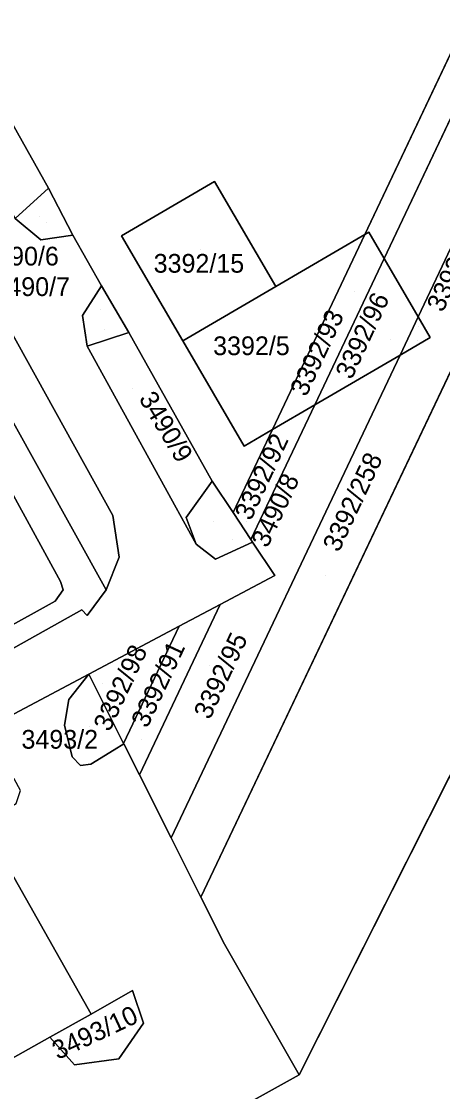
# Model space of a CAD drawing. Extents: x -262715 to -259381, y -1237238 to -1231182.
# Drawn here: x -261261.3 to -261216.3, y -1235699.9 to -1235585.6 of the extents above; entities that cross this region are included whole.
import ezdxf

# ---------------------------------------------------------------- set-up
doc = ezdxf.new("R2010")
doc.units = 0
for name, color, linetype in [('body_kn', 7, 'Continuous'), ('kladpar_druhypozemkov', 7, 'Continuous'), ('kladpar_hranice', 7, 'Continuous'), ('kladpar_parcelnecisla', 7, 'Continuous'), ('kladpar_plochy', 7, 'Continuous'), ('kladpar_sipky', 7, 'Continuous'), ('zuob_linie', 7, 'Continuous'), ('zuob_plochy', 7, 'Continuous')]:
    doc.layers.add(name, color=color, linetype=linetype)

msp = doc.modelspace()

# ---------------------------------------------------------------- linework, layer by layer
at = {"layer": 'body_kn'}
for p, q in [((-261240.67, -1235602.69), (-261240.67, -1235602.69)), ((-261258.41, -1235603.43), (-261258.41, -1235603.43)), ((-261258.41, -1235603.43), (-261258.41, -1235603.43)), ((-261224.62, -1235608.37), (-261224.62, -1235608.37)), ((-261224.62, -1235608.37), (-261224.62, -1235608.37)), ((-261224.19, -1235608.12), (-261224.19, -1235608.12)), ((-261259.21, -1235608.94), (-261259.21, -1235608.94)), ((-261255.82, -1235608.45), (-261255.82, -1235608.45)), ((-261250.6, -1235608.49), (-261250.6, -1235608.49)), ((-261250.6, -1235608.49), (-261250.6, -1235608.49)), ((-261222.56, -1235610.92), (-261222.56, -1235610.92)), ((-261252.75, -1235613.83), (-261252.75, -1235613.83)), ((-261252.75, -1235613.83), (-261252.75, -1235613.83)), ((-261234.12, -1235613.92), (-261234.12, -1235613.92)), ((-261254.78, -1235617), (-261254.78, -1235617)), ((-261218.92, -1235617.15), (-261218.92, -1235617.15)), ((-261218.92, -1235617.15), (-261218.92, -1235617.15)), ((-261249.83, -1235618.82), (-261249.83, -1235618.82)), ((-261249.83, -1235618.82), (-261249.83, -1235618.82)), ((-261244.05, -1235619.72), (-261244.05, -1235619.72)), ((-261217.63, -1235619.35), (-261217.63, -1235619.35)), ((-261254.29, -1235620.3), (-261254.29, -1235620.3)), ((-261220.86, -1235621.23), (-261220.86, -1235621.23)), ((-261220.86, -1235621.23), (-261220.86, -1235621.23)), ((-261227.57, -1235625.15), (-261227.57, -1235625.15)), ((-261229.97, -1235626.55), (-261229.97, -1235626.55)), ((-261234.49, -1235629.19), (-261234.49, -1235629.19)), ((-261234.49, -1235629.19), (-261234.49, -1235629.19)), ((-261237.5, -1235630.95), (-261237.5, -1235630.95)), ((-261237.5, -1235630.95), (-261237.5, -1235630.95)), ((-261240.92, -1235634.68), (-261240.92, -1235634.68)), ((-261240.92, -1235634.68), (-261240.92, -1235634.68)), ((-261238.69, -1235638.05), (-261238.69, -1235638.05)), ((-261238.69, -1235638.05), (-261238.69, -1235638.05)), ((-261251.55, -1235638.37), (-261251.55, -1235638.37)), ((-261243.7, -1235638.58), (-261243.7, -1235638.58)), ((-261242.62, -1235641.42), (-261242.62, -1235641.42)), ((-261236.79, -1235640.93), (-261236.79, -1235640.93)), ((-261236.79, -1235640.93), (-261236.79, -1235640.93)), ((-261236.6, -1235641.21), (-261236.6, -1235641.21)), ((-261250.84, -1235642.82), (-261250.84, -1235642.82)), ((-261240.57, -1235643.03), (-261240.57, -1235643.03)), ((-261234.24, -1235644.77), (-261234.24, -1235644.77)), ((-261234.24, -1235644.77), (-261234.24, -1235644.77)), ((-261257.11, -1235645.41), (-261257.11, -1235645.41)), ((-261256.83, -1235646.31), (-261256.83, -1235646.31)), ((-261252.24, -1235646.28), (-261252.24, -1235646.28)), ((-261257.7, -1235647.52), (-261257.7, -1235647.52)), ((-261240.08, -1235647.87), (-261240.08, -1235647.87)), ((-261240.08, -1235647.87), (-261240.08, -1235647.87)), ((-261254.86, -1235648.43), (-261254.86, -1235648.43)), ((-261254.29, -1235649.03), (-261254.29, -1235649.03)), ((-261244.44, -1235650.18), (-261244.44, -1235650.18)), ((-261244.44, -1235650.18), (-261244.44, -1235650.18)), ((-261254.11, -1235655.31), (-261254.11, -1235655.31)), ((-261254.11, -1235655.31), (-261254.11, -1235655.31)), ((-261256.24, -1235658.01), (-261256.24, -1235658.01)), ((-261256.68, -1235660.75), (-261256.68, -1235660.75)), ((-261250.38, -1235662.71), (-261250.38, -1235662.71)), ((-261250.38, -1235662.71), (-261250.38, -1235662.71)), ((-261250.37, -1235662.74), (-261250.37, -1235662.74)), ((-261250.37, -1235662.74), (-261250.37, -1235662.74)), ((-261255.86, -1235664.12), (-261255.86, -1235664.12)), ((-261251.4, -1235663.37), (-261251.4, -1235663.37)), ((-261254.97, -1235665.03), (-261254.97, -1235665.03)), ((-261253.87, -1235664.9), (-261253.87, -1235664.9)), ((-261248.7, -1235666.05), (-261248.7, -1235666.05)), ((-261248.7, -1235666.05), (-261248.7, -1235666.05)), ((-261245.32, -1235672.77), (-261245.32, -1235672.77)), ((-261245.32, -1235672.77), (-261245.32, -1235672.77)), ((-261242.13, -1235679.1), (-261242.13, -1235679.1)), ((-261242.13, -1235679.1), (-261242.13, -1235679.1)), ((-261239.6, -1235684.13), (-261239.6, -1235684.13)), ((-261249.44, -1235689.06), (-261249.44, -1235689.06)), ((-261249.44, -1235689.06), (-261249.44, -1235689.06)), ((-261253.85, -1235691.6), (-261253.85, -1235691.6)), ((-261248.26, -1235692.56), (-261248.26, -1235692.56)), ((-261258.25, -1235694.06), (-261258.25, -1235694.06)), ((-261250.88, -1235696.36), (-261250.88, -1235696.36)), ((-261255.62, -1235697), (-261255.62, -1235697)), ((-261231.63, -1235698.08), (-261231.63, -1235698.08)), ((-261231.63, -1235698.08), (-261231.63, -1235698.08))]:
    msp.add_line(p, q, dxfattribs=at)
at = {"layer": 'kladpar_druhypozemkov'}
for p, q in [((-261259.35, -1235606.46), (-261259.35, -1235606.46)), ((-261242.15, -1235609.92), (-261242.15, -1235609.92)), ((-261225.77, -1235614.44), (-261225.77, -1235614.44)), ((-261252.47, -1235618.53), (-261252.47, -1235618.53)), ((-261236.51, -1235618.92), (-261236.51, -1235618.92)), ((-261221.89, -1235619.62), (-261221.89, -1235619.62)), ((-261219.02, -1235619.72), (-261219.02, -1235619.72)), ((-261249.41, -1235624.85), (-261249.41, -1235624.85)), ((-261240.81, -1235639.03), (-261240.81, -1235639.03)), ((-261237.23, -1235639.02), (-261237.23, -1235639.02)), ((-261228.83, -1235644.72), (-261228.83, -1235644.72)), ((-261241.2, -1235654.39), (-261241.2, -1235654.39)), ((-261252.66, -1235656.24), (-261252.66, -1235656.24)), ((-261254.07, -1235660.88), (-261254.07, -1235660.88)), ((-261248.51, -1235662.29), (-261248.51, -1235662.29)), ((-261253.4, -1235692.73), (-261253.4, -1235692.73))]:
    msp.add_line(p, q, dxfattribs=at)
at = {"layer": 'kladpar_hranice'}
for p, q in [((-261121.43, -1235479.48), (-261231.63, -1235698.08)), ((-261165.83, -1235491.3), (-261222.56, -1235610.92)), ((-261222.56, -1235610.92), (-261165.83, -1235491.3)), ((-261224.62, -1235608.37), (-261169.58, -1235492.3)), ((-261169.58, -1235492.3), (-261224.62, -1235608.37)), ((-261198.15, -1235586.57), (-261242.13, -1235679.1)), ((-261242.13, -1235679.1), (-261198.15, -1235586.57)), ((-261218.92, -1235617.15), (-261206.8, -1235591.61)), ((-261234.49, -1235629.19), (-261224.62, -1235608.37)), ((-261224.62, -1235608.37), (-261234.49, -1235629.19)), ((-261222.56, -1235610.92), (-261229.97, -1235626.55)), ((-261229.97, -1235626.55), (-261222.56, -1235610.92)), ((-261222.56, -1235610.92), (-261218.92, -1235617.15)), ((-261218.92, -1235617.15), (-261222.56, -1235610.92)), ((-261218.92, -1235617.15), (-261220.86, -1235621.23)), ((-261220.86, -1235621.23), (-261218.92, -1235617.15)), ((-261220.86, -1235621.23), (-261245.32, -1235672.77)), ((-261245.32, -1235672.77), (-261220.86, -1235621.23)), ((-261236.79, -1235640.93), (-261229.97, -1235626.55)), ((-261229.97, -1235626.55), (-261236.79, -1235640.93)), ((-261234.49, -1235629.19), (-261229.97, -1235626.55)), ((-261229.97, -1235626.55), (-261234.49, -1235629.19)), ((-261238.69, -1235638.05), (-261234.49, -1235629.19)), ((-261234.49, -1235629.19), (-261238.69, -1235638.05)), ((-261234.49, -1235629.19), (-261237.5, -1235630.95)), ((-261236.79, -1235640.93), (-261238.69, -1235638.05)), ((-261240.08, -1235647.87), (-261234.24, -1235644.77)), ((-261240.08, -1235647.87), (-261248.7, -1235666.05)), ((-261248.7, -1235666.05), (-261240.08, -1235647.87)), ((-261244.44, -1235650.18), (-261240.08, -1235647.87)), ((-261244.44, -1235650.18), (-261250.38, -1235662.71)), ((-261250.38, -1235662.71), (-261244.44, -1235650.18)), ((-261245.32, -1235672.77), (-261248.7, -1235666.05)), ((-261242.13, -1235679.1), (-261245.32, -1235672.77)), ((-261231.63, -1235698.08), (-261247.32, -1235706.78))]:
    msp.add_line(p, q, dxfattribs=at)
for points in [[(-261342.66, -1235927.5), (-261305.98, -1235847.48), (-261286.88, -1235811.21), (-261270.21, -1235802.65), (-261261.41, -1235789.19), (-261264.64, -1235782.74), (-261232.23, -1235764.3), (-261246.53, -1235736.08), (-261244.04, -1235715.2), (-261247.32, -1235706.78), (-261231.63, -1235698.08), (-261121.43, -1235479.48), (-261091.67, -1235469.74), (-261012.03, -1235427.74)], [(-261348.7, -1235700.98), (-261254.86, -1235648.43), (-261254.29, -1235649.03), (-261252.24, -1235646.28), (-261250.84, -1235642.82), (-261251.55, -1235638.37), (-261278.31, -1235590.06), (-261297.76, -1235555.37), (-261300.62, -1235557.17), (-261303.29, -1235552.52), (-261300.28, -1235550.68), (-261302.53, -1235546.52), (-261305.55, -1235548.27), (-261308.61, -1235542.94), (-261305.57, -1235541.1), (-261321.66, -1235512.26), (-261351.08, -1235459.4), (-261354.39, -1235456.61), (-261358.31, -1235454.86), (-261362.69, -1235454.33), (-261368.97, -1235455.57), (-261351.54, -1235445.98)], [(-261358.31, -1235454.86), (-261354.39, -1235456.61), (-261351.08, -1235459.4), (-261321.66, -1235512.26), (-261305.57, -1235541.1), (-261308.61, -1235542.94), (-261305.55, -1235548.27), (-261302.53, -1235546.52), (-261300.28, -1235550.68), (-261303.29, -1235552.52), (-261300.62, -1235557.17), (-261297.76, -1235555.37), (-261278.31, -1235590.06), (-261251.55, -1235638.37), (-261250.84, -1235642.82), (-261252.24, -1235646.28), (-261282.88, -1235591.22), (-261325.69, -1235513.96), (-261358.31, -1235454.86)], [(-261358.31, -1235454.86), (-261325.69, -1235513.96), (-261282.88, -1235591.22), (-261252.24, -1235646.28), (-261254.29, -1235649.03), (-261254.86, -1235648.43), (-261348.7, -1235700.98)], [(-261333.04, -1235479.2), (-261302.29, -1235534.31), (-261299.79, -1235536.41), (-261296.24, -1235536.01), (-261293.09, -1235541.55), (-261295.24, -1235544.28), (-261294.94, -1235547.45), (-261261.95, -1235606.65), (-261259.21, -1235608.94), (-261255.82, -1235608.45), (-261252.75, -1235613.83), (-261254.78, -1235617), (-261254.29, -1235620.3), (-261242.62, -1235641.42), (-261240.57, -1235643.03), (-261236.6, -1235641.21), (-261234.24, -1235644.77), (-261240.08, -1235647.87), (-261244.44, -1235650.18), (-261254.11, -1235655.31), (-261271.74, -1235664.65), (-261270.81, -1235669.39), (-261320.5, -1235697.56), (-261344.58, -1235711.11)], [(-261158.21, -1235489.27), (-261194.87, -1235566.5), (-261206.8, -1235591.61), (-261218.92, -1235617.15)], [(-261290.26, -1235546.58), (-261284.04, -1235557.68), (-261279.79, -1235565.26), (-261258.41, -1235603.43), (-261261.95, -1235606.65), (-261294.94, -1235547.45), (-261290.26, -1235546.58)], [(-261238.69, -1235638.05), (-261240.92, -1235634.68), (-261249.83, -1235618.82), (-261252.75, -1235613.83), (-261255.82, -1235608.45), (-261258.41, -1235603.43), (-261279.79, -1235565.26)], [(-261250.6, -1235608.49), (-261240.67, -1235602.69), (-261234.12, -1235613.92), (-261244.05, -1235619.72), (-261250.6, -1235608.49)], [(-261224.62, -1235608.37), (-261234.12, -1235613.92), (-261240.67, -1235602.69), (-261250.6, -1235608.49), (-261244.05, -1235619.72), (-261237.5, -1235630.95), (-261234.49, -1235629.19)], [(-261258.41, -1235603.43), (-261255.82, -1235608.45), (-261259.21, -1235608.94), (-261261.95, -1235606.65), (-261258.41, -1235603.43)], [(-261237.5, -1235630.95), (-261244.05, -1235619.72), (-261234.12, -1235613.92), (-261224.62, -1235608.37)], [(-261224.62, -1235608.37), (-261224.19, -1235608.12), (-261222.56, -1235610.92)], [(-261222.56, -1235610.92), (-261224.19, -1235608.12), (-261224.62, -1235608.37)], [(-261252.75, -1235613.83), (-261249.83, -1235618.82), (-261254.29, -1235620.3), (-261254.78, -1235617), (-261252.75, -1235613.83)], [(-261220.86, -1235621.23), (-261217.63, -1235619.35), (-261218.92, -1235617.15)], [(-261218.92, -1235617.15), (-261217.63, -1235619.35), (-261220.86, -1235621.23)], [(-261249.83, -1235618.82), (-261240.92, -1235634.68), (-261243.7, -1235638.58), (-261242.62, -1235641.42), (-261254.29, -1235620.3), (-261249.83, -1235618.82)], [(-261229.97, -1235626.55), (-261227.57, -1235625.15), (-261220.86, -1235621.23)], [(-261220.86, -1235621.23), (-261227.57, -1235625.15), (-261229.97, -1235626.55)], [(-261281.1, -1235660.46), (-261257.7, -1235647.52), (-261256.83, -1235646.31), (-261257.11, -1235645.41), (-261263.65, -1235633.57)], [(-261263.65, -1235633.57), (-261257.11, -1235645.41), (-261256.83, -1235646.31), (-261257.7, -1235647.52), (-261281.1, -1235660.46)], [(-261240.92, -1235634.68), (-261238.69, -1235638.05), (-261236.79, -1235640.93), (-261236.6, -1235641.21), (-261240.57, -1235643.03), (-261242.62, -1235641.42), (-261243.7, -1235638.58), (-261240.92, -1235634.68)], [(-261234.24, -1235644.77), (-261236.6, -1235641.21), (-261236.79, -1235640.93)], [(-261250.38, -1235662.71), (-261254.11, -1235655.31), (-261244.44, -1235650.18)], [(-261262.61, -1235700.75), (-261263.38, -1235696.93), (-261258.25, -1235694.06), (-261255.62, -1235697), (-261250.88, -1235696.36), (-261248.26, -1235692.56), (-261249.44, -1235689.06), (-261253.85, -1235691.6), (-261265.41, -1235671.17), (-261261.86, -1235669.1), (-261261.41, -1235667.7), (-261262.08, -1235666.47), (-261264.45, -1235664.33), (-261268.12, -1235663.52), (-261271.74, -1235664.65), (-261254.11, -1235655.31)], [(-261250.37, -1235662.74), (-261251.4, -1235663.37), (-261253.87, -1235664.9), (-261254.97, -1235665.03), (-261255.86, -1235664.12), (-261256.68, -1235660.75), (-261256.24, -1235658.01), (-261254.11, -1235655.31), (-261250.38, -1235662.71), (-261250.37, -1235662.74)], [(-261254.11, -1235655.31), (-261256.24, -1235658.01), (-261256.68, -1235660.75), (-261255.86, -1235664.12), (-261254.97, -1235665.03), (-261253.87, -1235664.9), (-261251.4, -1235663.37), (-261250.37, -1235662.74), (-261248.7, -1235666.05), (-261245.32, -1235672.77), (-261242.13, -1235679.1), (-261239.6, -1235684.13), (-261231.63, -1235698.08)], [(-261248.7, -1235666.05), (-261250.37, -1235662.74), (-261250.38, -1235662.71)], [(-261265.41, -1235671.17), (-261253.85, -1235691.6), (-261258.25, -1235694.06), (-261263.38, -1235696.93), (-261267.72, -1235699.4), (-261272.07, -1235701.8), (-261277.42, -1235704.85), (-261281.62, -1235707.12), (-261285.9, -1235709.58), (-261291.38, -1235712.65), (-261295.63, -1235715.04), (-261307.28, -1235694.75), (-261293.18, -1235686.93), (-261279.26, -1235678.99), (-261265.41, -1235671.17)], [(-261231.63, -1235698.08), (-261239.6, -1235684.13), (-261242.13, -1235679.1)], [(-261249.44, -1235689.06), (-261248.26, -1235692.56), (-261250.88, -1235696.36), (-261255.62, -1235697), (-261258.25, -1235694.06), (-261253.85, -1235691.6), (-261249.44, -1235689.06)]]:
    msp.add_lwpolyline(points, dxfattribs=at)
at = {"layer": 'kladpar_plochy'}
for points in [[(-261342.66, -1235927.5), (-261305.98, -1235847.48), (-261286.88, -1235811.21), (-261270.21, -1235802.65), (-261261.41, -1235789.19), (-261264.64, -1235782.74), (-261232.23, -1235764.3), (-261246.53, -1235736.08), (-261244.04, -1235715.2), (-261247.32, -1235706.78), (-261231.63, -1235698.08), (-261121.43, -1235479.48), (-261091.67, -1235469.74), (-261012.03, -1235427.74)], [(-261358.31, -1235454.86), (-261325.69, -1235513.96), (-261282.88, -1235591.22), (-261252.24, -1235646.28), (-261254.29, -1235649.03), (-261254.86, -1235648.43), (-261348.7, -1235700.98)], [(-261348.7, -1235700.98), (-261254.86, -1235648.43), (-261254.29, -1235649.03), (-261252.24, -1235646.28), (-261250.84, -1235642.82), (-261251.55, -1235638.37), (-261278.31, -1235590.06), (-261297.76, -1235555.37), (-261300.62, -1235557.17), (-261303.29, -1235552.52), (-261300.28, -1235550.68), (-261302.53, -1235546.52), (-261305.55, -1235548.27), (-261308.61, -1235542.94), (-261305.57, -1235541.1), (-261321.66, -1235512.26), (-261351.08, -1235459.4)], [(-261333.04, -1235479.2), (-261302.29, -1235534.31), (-261299.79, -1235536.41), (-261296.24, -1235536.01), (-261293.09, -1235541.55), (-261295.24, -1235544.28), (-261294.94, -1235547.45), (-261261.95, -1235606.65), (-261259.21, -1235608.94), (-261255.82, -1235608.45), (-261252.75, -1235613.83), (-261254.78, -1235617), (-261254.29, -1235620.3), (-261242.62, -1235641.42), (-261240.57, -1235643.03), (-261236.6, -1235641.21), (-261234.24, -1235644.77), (-261240.08, -1235647.87), (-261244.44, -1235650.18), (-261254.11, -1235655.31), (-261271.74, -1235664.65), (-261270.81, -1235669.39), (-261320.5, -1235697.56), (-261344.58, -1235711.11)], [(-261169.58, -1235492.3), (-261224.62, -1235608.37), (-261234.12, -1235613.92), (-261240.67, -1235602.69), (-261250.6, -1235608.49), (-261244.05, -1235619.72), (-261237.5, -1235630.95), (-261234.49, -1235629.19), (-261238.69, -1235638.05), (-261240.92, -1235634.68), (-261249.83, -1235618.82), (-261252.75, -1235613.83), (-261255.82, -1235608.45), (-261258.41, -1235603.43), (-261279.79, -1235565.26)], [(-261281.1, -1235660.46), (-261257.7, -1235647.52), (-261256.83, -1235646.31), (-261257.11, -1235645.41), (-261263.65, -1235633.57)], [(-261263.65, -1235633.57), (-261257.11, -1235645.41), (-261256.83, -1235646.31), (-261257.7, -1235647.52), (-261281.1, -1235660.46)], [(-261271.74, -1235664.65), (-261254.11, -1235655.31), (-261256.24, -1235658.01), (-261256.68, -1235660.75), (-261255.86, -1235664.12), (-261254.97, -1235665.03), (-261253.87, -1235664.9), (-261251.4, -1235663.37), (-261250.37, -1235662.74), (-261248.7, -1235666.05), (-261245.32, -1235672.77), (-261242.13, -1235679.1), (-261239.6, -1235684.13), (-261231.63, -1235698.08), (-261247.32, -1235706.78)], [(-261263.38, -1235696.93), (-261258.25, -1235694.06), (-261255.62, -1235697), (-261250.88, -1235696.36), (-261248.26, -1235692.56), (-261249.44, -1235689.06), (-261253.85, -1235691.6), (-261265.41, -1235671.17)]]:
    msp.add_lwpolyline(points, dxfattribs=at)
for points in [[(-261358.31, -1235454.86), (-261354.39, -1235456.61), (-261351.08, -1235459.4), (-261321.66, -1235512.26), (-261305.57, -1235541.1), (-261308.61, -1235542.94), (-261305.55, -1235548.27), (-261302.53, -1235546.52), (-261300.28, -1235550.68), (-261303.29, -1235552.52), (-261300.62, -1235557.17), (-261297.76, -1235555.37), (-261278.31, -1235590.06), (-261251.55, -1235638.37), (-261250.84, -1235642.82), (-261252.24, -1235646.28), (-261282.88, -1235591.22), (-261325.69, -1235513.96)], [(-261141.45, -1235484.81), (-261138.41, -1235484), (-261121.43, -1235479.48), (-261231.63, -1235698.08), (-261239.6, -1235684.13), (-261242.13, -1235679.1), (-261198.15, -1235586.57), (-261206.8, -1235591.61), (-261194.87, -1235566.5), (-261191.45, -1235572.47), (-261150.99, -1235487.35)], [(-261158.21, -1235489.27), (-261194.87, -1235566.5), (-261206.8, -1235591.61), (-261218.92, -1235617.15), (-261222.56, -1235610.92), (-261165.83, -1235491.3)], [(-261224.62, -1235608.37), (-261169.58, -1235492.3), (-261165.83, -1235491.3), (-261222.56, -1235610.92), (-261224.19, -1235608.12)], [(-261290.26, -1235546.58), (-261284.04, -1235557.68), (-261279.79, -1235565.26), (-261258.41, -1235603.43), (-261261.95, -1235606.65), (-261294.94, -1235547.45)], [(-261218.92, -1235617.15), (-261206.8, -1235591.61), (-261198.15, -1235586.57), (-261242.13, -1235679.1), (-261245.32, -1235672.77), (-261220.86, -1235621.23), (-261217.63, -1235619.35)], [(-261250.6, -1235608.49), (-261240.67, -1235602.69), (-261234.12, -1235613.92), (-261244.05, -1235619.72)], [(-261258.41, -1235603.43), (-261255.82, -1235608.45), (-261259.21, -1235608.94), (-261261.95, -1235606.65)], [(-261237.5, -1235630.95), (-261244.05, -1235619.72), (-261234.12, -1235613.92), (-261224.62, -1235608.37), (-261234.49, -1235629.19)], [(-261234.49, -1235629.19), (-261224.62, -1235608.37), (-261224.19, -1235608.12), (-261222.56, -1235610.92), (-261229.97, -1235626.55)], [(-261218.92, -1235617.15), (-261220.86, -1235621.23), (-261227.57, -1235625.15), (-261229.97, -1235626.55), (-261222.56, -1235610.92)], [(-261252.75, -1235613.83), (-261249.83, -1235618.82), (-261254.29, -1235620.3), (-261254.78, -1235617)], [(-261220.86, -1235621.23), (-261218.92, -1235617.15), (-261217.63, -1235619.35)], [(-261249.83, -1235618.82), (-261240.92, -1235634.68), (-261243.7, -1235638.58), (-261242.62, -1235641.42), (-261254.29, -1235620.3)], [(-261234.24, -1235644.77), (-261236.6, -1235641.21), (-261236.79, -1235640.93), (-261229.97, -1235626.55), (-261227.57, -1235625.15), (-261220.86, -1235621.23), (-261245.32, -1235672.77), (-261248.7, -1235666.05), (-261240.08, -1235647.87)], [(-261238.69, -1235638.05), (-261234.49, -1235629.19), (-261229.97, -1235626.55), (-261236.79, -1235640.93)], [(-261240.92, -1235634.68), (-261238.69, -1235638.05), (-261236.79, -1235640.93), (-261236.6, -1235641.21), (-261240.57, -1235643.03), (-261242.62, -1235641.42), (-261243.7, -1235638.58)], [(-261240.08, -1235647.87), (-261248.7, -1235666.05), (-261250.37, -1235662.74), (-261250.38, -1235662.71), (-261244.44, -1235650.18)], [(-261244.44, -1235650.18), (-261250.38, -1235662.71), (-261254.11, -1235655.31)], [(-261250.37, -1235662.74), (-261251.4, -1235663.37), (-261253.87, -1235664.9), (-261254.97, -1235665.03), (-261255.86, -1235664.12), (-261256.68, -1235660.75), (-261256.24, -1235658.01), (-261254.11, -1235655.31), (-261250.38, -1235662.71)], [(-261265.41, -1235671.17), (-261253.85, -1235691.6), (-261258.25, -1235694.06), (-261263.38, -1235696.93), (-261267.72, -1235699.4), (-261272.07, -1235701.8), (-261277.42, -1235704.85), (-261281.62, -1235707.12), (-261285.9, -1235709.58), (-261291.38, -1235712.65), (-261295.63, -1235715.04), (-261307.28, -1235694.75), (-261293.18, -1235686.93), (-261279.26, -1235678.99)], [(-261249.44, -1235689.06), (-261248.26, -1235692.56), (-261250.88, -1235696.36), (-261255.62, -1235697), (-261258.25, -1235694.06), (-261253.85, -1235691.6)]]:
    msp.add_lwpolyline(points, close=True, dxfattribs=at)
at = {"layer": 'kladpar_sipky'}
for p, q in [((-261258.59, -1235607.03), (-261258.59, -1235607.03)), ((-261252.85, -1235616.42), (-261252.85, -1235616.42)), ((-261218.86, -1235618.16), (-261218.86, -1235618.16)), ((-261238.7, -1235640.95), (-261238.7, -1235640.95))]:
    msp.add_line(p, q, dxfattribs=at)
at = {"layer": 'zuob_linie'}
for points in [[(-261342.66, -1235927.5), (-261305.98, -1235847.48), (-261286.88, -1235811.21), (-261270.21, -1235802.65), (-261261.41, -1235789.19), (-261264.64, -1235782.74), (-261232.23, -1235764.3), (-261246.53, -1235736.08), (-261244.04, -1235715.2), (-261247.32, -1235706.78), (-261231.63, -1235698.08), (-261121.43, -1235479.48), (-261138.41, -1235484), (-261141.45, -1235484.81), (-261150.99, -1235487.35), (-261158.21, -1235489.27), (-261165.83, -1235491.3), (-261169.58, -1235492.3), (-261172.8, -1235493.16), (-261196.8, -1235492.84), (-261220, -1235476.4), (-261256.2, -1235473.7), (-261380.11, -1235367.49)], [(-261380.11, -1235367.49), (-261256.2, -1235473.7), (-261220, -1235476.4), (-261196.8, -1235492.84), (-261172.8, -1235493.16), (-261169.58, -1235492.3), (-261165.83, -1235491.3), (-261158.21, -1235489.27), (-261150.99, -1235487.35), (-261141.45, -1235484.81), (-261138.41, -1235484), (-261121.43, -1235479.48), (-261231.63, -1235698.08), (-261247.32, -1235706.78), (-261244.04, -1235715.2), (-261246.53, -1235736.08), (-261232.23, -1235764.3), (-261264.64, -1235782.74), (-261261.41, -1235789.19), (-261270.21, -1235802.65), (-261286.88, -1235811.21), (-261305.98, -1235847.48), (-261342.66, -1235927.5)]]:
    msp.add_lwpolyline(points, dxfattribs=at)
at = {"layer": 'zuob_plochy'}
for points in [[(-261342.66, -1235927.5), (-261305.98, -1235847.48), (-261286.88, -1235811.21), (-261270.21, -1235802.65), (-261261.41, -1235789.19), (-261264.64, -1235782.74), (-261232.23, -1235764.3), (-261246.53, -1235736.08), (-261244.04, -1235715.2), (-261247.32, -1235706.78), (-261231.63, -1235698.08), (-261121.43, -1235479.48), (-261138.41, -1235484), (-261141.45, -1235484.81), (-261150.99, -1235487.35), (-261158.21, -1235489.27), (-261165.83, -1235491.3), (-261169.58, -1235492.3), (-261172.8, -1235493.16), (-261196.8, -1235492.84), (-261220, -1235476.4), (-261256.2, -1235473.7), (-261380.11, -1235367.49)], [(-261380.11, -1235367.49), (-261256.2, -1235473.7), (-261220, -1235476.4), (-261196.8, -1235492.84), (-261172.8, -1235493.16), (-261169.58, -1235492.3), (-261165.83, -1235491.3), (-261158.21, -1235489.27), (-261150.99, -1235487.35), (-261141.45, -1235484.81), (-261138.41, -1235484), (-261121.43, -1235479.48), (-261231.63, -1235698.08), (-261247.32, -1235706.78), (-261244.04, -1235715.2), (-261246.53, -1235736.08), (-261232.23, -1235764.3), (-261264.64, -1235782.74), (-261261.41, -1235789.19), (-261270.21, -1235802.65), (-261286.88, -1235811.21), (-261305.98, -1235847.48), (-261342.66, -1235927.5)]]:
    msp.add_lwpolyline(points, dxfattribs=at)

# ---------------------------------------------------------------- texts
at = {"layer": 'kladpar_parcelnecisla'}
for s, rotation, p in [('3392/4', 65, (-261216.29, -1235616.76)), ('3392/96', 65, (-261226.03, -1235623.94)), ('3392/93', 65, (-261230.88, -1235625.77)), ('3490/9', 301, (-261248.81, -1235625.88)), ('3392/92', 65, (-261236.79, -1235639)), ('3392/258', 65, (-261227.39, -1235642.37)), ('3490/8', 65, (-261235.02, -1235641.91)), ('3392/95', 65, (-261241.17, -1235660.24)), ('3392/98', 65, (-261251.88, -1235661.54)), ('3392/91', 65, (-261247.85, -1235661.15)), ('3493/10', 25, (-261257.42, -1235696.49))]:
    msp.add_text(s, height=2, rotation=rotation, dxfattribs=at).set_placement(p)
for s, p in [('3490/6', (-261265.48, -1235611.67)), ('3392/15', (-261247.17, -1235612.44)), ('3490/7', (-261264.29, -1235614.93)), ('3392/5', (-261240.82, -1235621.24)), ('3493/2', (-261261.29, -1235663.25))]:
    msp.add_text(s, height=2, dxfattribs=at).set_placement(p)

doc.saveas('drawing.dxf')
